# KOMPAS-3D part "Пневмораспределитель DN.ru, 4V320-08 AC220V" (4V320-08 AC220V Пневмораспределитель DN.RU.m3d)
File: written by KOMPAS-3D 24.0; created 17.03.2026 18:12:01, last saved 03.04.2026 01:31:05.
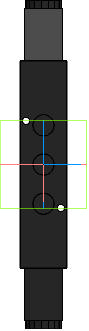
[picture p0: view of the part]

Document properties: Автор: R2D2; Полное имя файла: E:\Работа\Зайцев\Аксессуары для пневмоприводов\Пневмораспределители DN.ru\4V320 AC220V Пневмораспределитель DN.RU\4V320-08 AC220V Пневмораспределитель DN.RU\исходные материалы\4V320-08 AC220V Пневмораспределитель DN.RU.m3d

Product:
- Body: Тело 1  | qty 1
    Масса: 1.574255
- Body: Тело 3  | qty 1
    Масса: 1.574255
- Part/product: Пневмораспределитель DN.ru  | designation 4V320-08 AC220V
    Масса: 1.2
    Раздел спецификации: Прочие изделия
    Примечание: D290-00334

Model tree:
1. Эскиз:1
2. Элемент выдавливания:1
     Расстояние 1 = 118.8
3. Эскиз:2  (with: Грань.Элемент выдавливания:1)
4. Элемент выдавливания:2
     Расстояние 2 = 1.4
5. Эскиз:3  (with: Грань.Элемент выдавливания:1, Ребро.Элемент выдавливания:1)
6. Элемент выдавливания:3
     Расстояние 2 = 27
7. Эскиз:4  (with: Грань.Элемент выдавливания:1, Ребро.Элемент выдавливания:1)
8. Элемент выдавливания:4
     Расстояние 1 = 30
9. Эскиз:5  (with: Грань.Элемент выдавливания:4, Ребро.Элемент выдавливания:4)
10. Элемент выдавливания:5
     Расстояние 1 = 27
11. Эскиз:6  (with: Грань.Элемент выдавливания:4)
12. Элемент выдавливания:6
     Расстояние 1 = 5
13. Эскиз:7  (with: Грань.Элемент выдавливания:5)
14. Элемент выдавливания:7
     Расстояние 1 = 14
15. Эскиз:8  (with: Грань.Элемент выдавливания:7, Ребро.Элемент выдавливания:7)
16. Элемент выдавливания:8
     Расстояние 1 = 5
17. Эскиз:9  (with: Грань.Элемент выдавливания:1, Ребро.Элемент выдавливания:4)
18. Элемент выдавливания:9
     Расстояние 1 = 2.4
19. Эскиз:12  (with: Грань.Элемент выдавливания:9, Ребро.Элемент выдавливания:9)
20. Элемент выдавливания:12
     Расстояние 2 = 1
21. Эскиз:10  (with: Грань.Элемент выдавливания:1)
22. Элемент выдавливания:10
     Расстояние 2 = 12
23. пазы  (with: Грань.Элемент выдавливания:1, Ребро.Элемент выдавливания:3)
24. Элемент выдавливания:11
     Расстояние 2 = 5
25. Зеркальный массив:2
26. Экземпляр ( 1 )
27. Экземпляр ( 2 )  (with: Элемент выдавливания:4, Элемент выдавливания:6, Элемент выдавливания:5, Элемент выдавливания:7, Элемент выдавливания:8, Элемент выдавливания:9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)
28. Эскиз:13  (with: Грань.Элемент выдавливания:1)
29. Элемент выдавливания:13
     Расстояние 2 = 12
30. Эскиз:14  (with: Грань.Элемент выдавливания:1)  (labels: Вершина.Элемент выдавливания:6.Экземпляр ( 2 ))
31. Элемент выдавливания:14
     Расстояние 2 = 40
32. Эскиз:15  (with: Грань.Элемент выдавливания:1, Ребро.Элемент выдавливания:14)
33. Элемент выдавливания:15
     Расстояние 2 = 4

Expressions: 4V320-08 AC220V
